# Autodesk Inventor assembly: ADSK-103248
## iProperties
Shininess: 0.0
Created: 2000-12
Part Number: ADSK-103248
Document SubType Name: Assembly
Designer: gao
Stock Number: ADSK-103248
Density: 0.0
Volumn: 0.0
Area: 0.0
PropertySet Name: Model Information
Control State: 0
Master: False
Checked Out: False
Author: gao
